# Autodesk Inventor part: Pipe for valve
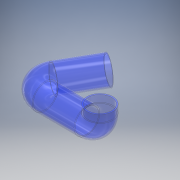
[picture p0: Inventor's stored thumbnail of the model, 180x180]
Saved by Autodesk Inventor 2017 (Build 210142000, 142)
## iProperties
Created: 2020-04
Part Number: Pipe for valve
Material: Polycarbonate, Clear
Document SubType Name: Modeling
Designer: user
Density: 1.2 g/cm^3
Appearance: Polycarbonate - Clear
Author: user
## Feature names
1. Sweep1
## Parameters: d0 = 15.96 mm, d1 = 42.28 mm, d4 = 60 deg, d6 = 1 mm, d7 = 0, d8 = 0
